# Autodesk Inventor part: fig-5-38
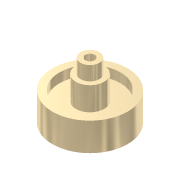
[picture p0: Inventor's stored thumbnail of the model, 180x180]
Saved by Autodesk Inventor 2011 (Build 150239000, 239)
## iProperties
Shininess: 65.0
Length Units: 11269
Angle Units: 11279
Time Units: 11290
Mass Units: 11283
Length Display Precision: 3
Angle Display Precision: 2
Created: 2001-11
Part Number: fig-5-38
Document SubType Name: Modeling
Designer: Renu Muthoo
Density: 1 g/cm^3
Density: 0.0
Volumn: 0.0
Area: 0.0
PropertySet Name: Model Information
Control State: 0
Master: False
Checked Out: False
Author: Renu Muthoo
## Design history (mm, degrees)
sketch "Sketch1"
  geometry: L1 (2.694, 30.112)-(5.194, 30.112); L2 (5.194, 30.112)-(5.194, 22.612); L3 (5.194, 22.612)-(7.694, 22.612); L4 (7.694, 22.612)-(7.694, 10.112); L5 (7.694, 10.112)-(16.444, 10.112); L6 (16.444, 10.112)-(16.444, 15.112); L7 (16.444, 15.112)-(20.194, 15.112); L8 (0.194, -4.034)-(0.194, 25.966); L9 (2.694, 30.112)-(2.694, 0.112); L10 (2.694, 0.112)-(20.194, 0.112); L11 (20.194, 0.112)-(20.194, 15.112)
  constraints: 22 end point, 7 parallel, 2 perpendicular, 1 horizontal
  dimensions: "d0" = 5 diameter of L9 L8; "d1" = 10 diameter of L2 L8; "d2" = 15 diameter of L4 L8; "d3" = 32.5 diameter of L6 L8; "d4" = 40 diameter of L11 L8; "d5" = 15 distance of L10.end L7.end; "d6" = 22.5 distance between parallel lines of L3 L10; "d7" = 30 distance between parallel lines of L1 L10; "d8" = 10 distance between parallel lines of L10 L5
revolve "Revolution1" sketch "Sketch1" stored, may be unused: angle "d9" = 90 deg
workaxis "Work Axis1"
node "Sketch3"
workaxis "Work Axis4"
body "Solid1"
